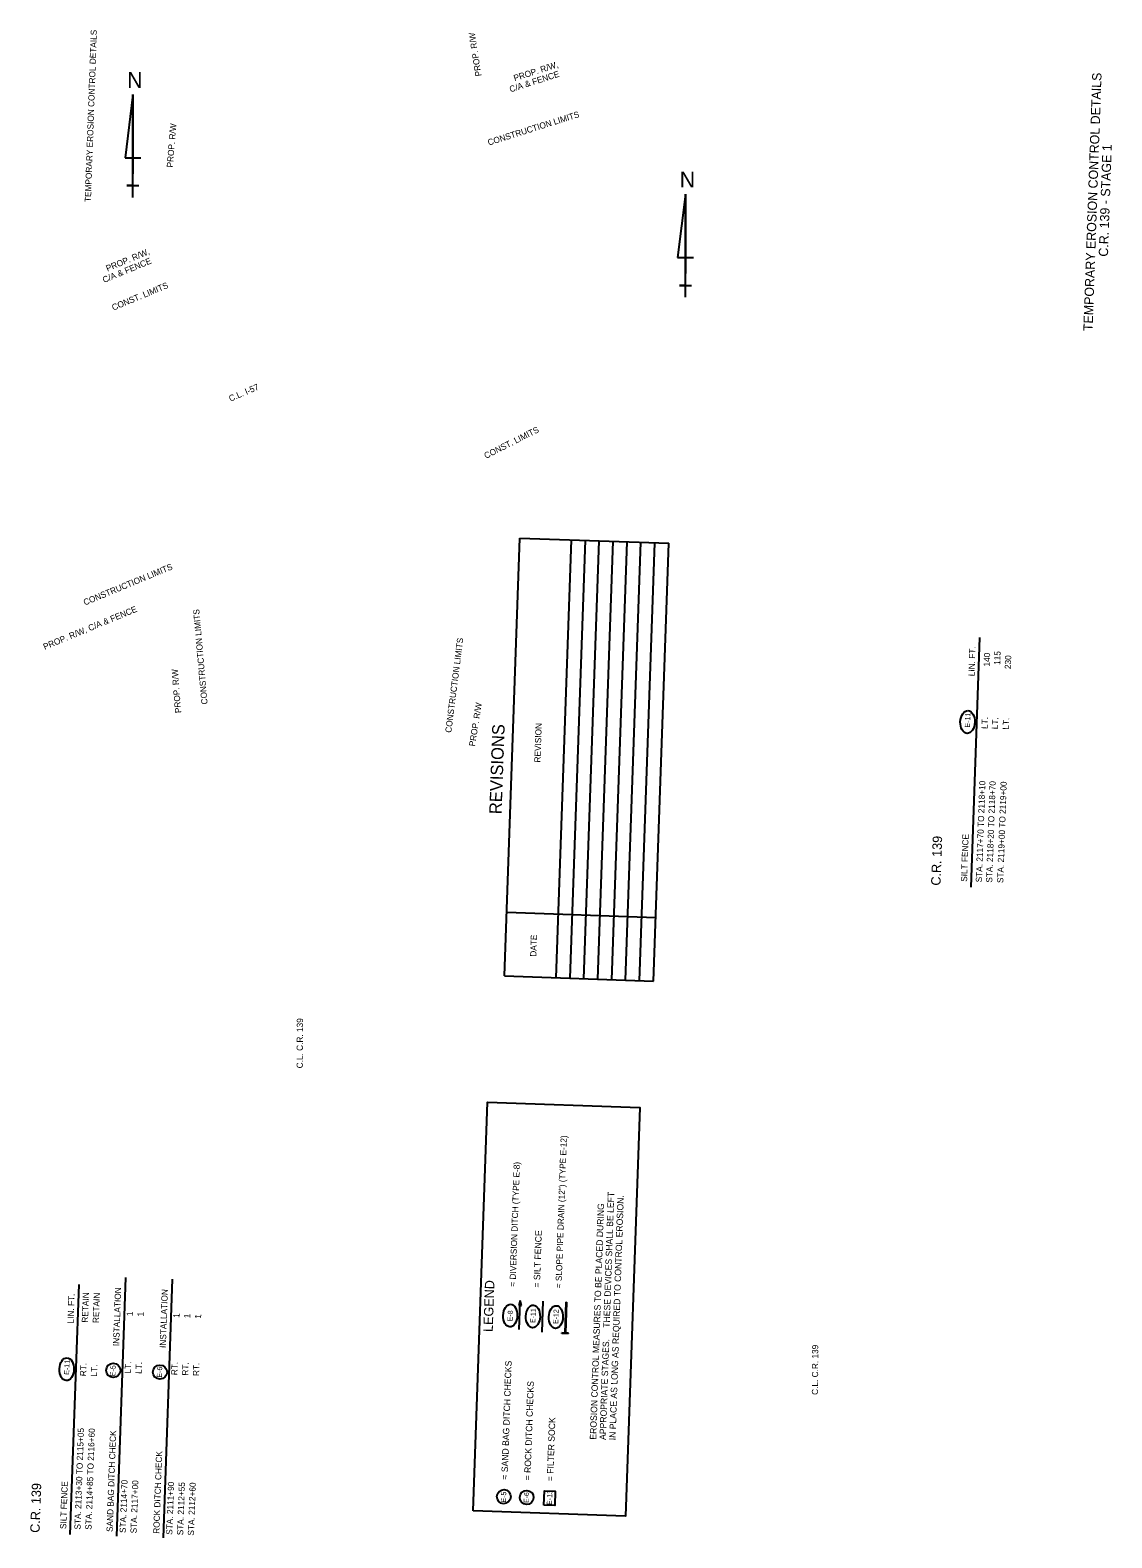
# Model space of a CAD drawing. Extents: x 1717345 to 1718395, y 765310 to 766772.
import ezdxf

# ---------------------------------------------------------------- set-up
doc = ezdxf.new("R2010")
doc.units = 0
for name, color, linetype in [('1', 7, 'Continuous'), ('44', 7, 'Continuous'), ('63', 7, 'Continuous'), ('Default', 7, 'Continuous'), ('G-ANNO-TEXT', 7, 'Continuous'), ('Level 1', 7, 'Continuous'), ('Level 44', 7, 'Continuous'), ('R_Draft', 7, 'Continuous')]:
    doc.layers.add(name, color=color, linetype=linetype)

msp = doc.modelspace()

# ---------------------------------------------------------------- linework, layer by layer
at = {"layer": '1'}
for points in [[(1717775.3, 765335.8), (1717789.1, 765732.2), (1717936.9, 765727), (1717923.1, 765330.6)], [(1717843.9, 765341.2), (1717844.4, 765355.2), (1717854.9, 765354.8), (1717854.4, 765340.8)]]:
    msp.add_lwpolyline(points, close=True, dxfattribs=at)
for centre in [(1717426, 765472), (1717471.3, 765470.3)]:
    msp.add_circle(centre, 6.88, dxfattribs=at)
for centre in [(1718255, 766100.8), (1717380.8, 765473.1)]:
    msp.add_ellipse(centre, major_axis=(0.4, 11), ratio=0.638788, dxfattribs=at)
at = {"layer": '44'}
for p, q in [((1718258.5, 765940.6), (1718267, 766182.9)), ((1717429.5, 765311.3), (1717438.2, 765562.2)), ((1717474.7, 765309.5), (1717483.5, 765560.4)), ((1717384.3, 765312.9), (1717392.8, 765555.2))]:
    msp.add_line(p, q, dxfattribs=at)
at = {"layer": '63'}
for p, q in [((1717445.1, 766709.4), (1717437.4, 766647.9)), ((1717445.1, 766609.4), (1717445.1, 766709.4)), ((1717445.1, 766709.4), (1717445.1, 766632.5)), ((1717437.4, 766647.9), (1717452.8, 766647.9)), ((1717445.1, 766609.4), (1717445.1, 766632.5)), ((1717445.1, 766621), (1717439.3, 766621)), ((1717439.3, 766621), (1717450.9, 766621)), ((1717445.1, 766609.4), (1717445.1, 766621)), ((1717981.3, 766612.8), (1717973.6, 766551.3)), ((1717981.3, 766512.8), (1717981.3, 766612.8)), ((1717981.3, 766612.8), (1717981.3, 766535.9)), ((1717973.6, 766551.3), (1717989, 766551.3)), ((1717981.3, 766524.3), (1717975.5, 766524.3)), ((1717975.5, 766524.3), (1717987.1, 766524.3)), ((1717981.3, 766512.8), (1717981.3, 766535.9)), ((1717981.3, 766512.8), (1717981.3, 766524.3))]:
    msp.add_line(p, q, dxfattribs=at)
at = {"layer": 'Default'}
for p, q in [((1717805.8, 765854.5), (1717820.6, 766279.2)), ((1717820.6, 766279.2), (1717965, 766274.2)), ((1717855.8, 765852.7), (1717870.6, 766277.5)), ((1717869.3, 765852.3), (1717884.1, 766277)), ((1717882.7, 765851.8), (1717897.6, 766276.5)), ((1717896.2, 765851.3), (1717911.1, 766276.1)), ((1717896.2, 765851.3), (1717911.1, 766276.1)), ((1717909.7, 765850.9), (1717924.6, 766275.6)), ((1717923.2, 765850.4), (1717938.1, 766275.1)), ((1717936.7, 765849.9), (1717951.5, 766274.7)), ((1717950.2, 765849.4), (1717965, 766274.2)), ((1717808, 765916.3), (1717952.4, 765911.2)), ((1717805.8, 765854.5), (1717950.2, 765849.4))]:
    msp.add_line(p, q, dxfattribs=at)
at = {"layer": 'Level 1'}
for p, q in [((1717821, 765539.7), (1717819.4, 765534.9)), ((1717819.4, 765534.9), (1717822.3, 765534.8)), ((1717820.7, 765538.4), (1717819.7, 765534.9)), ((1717820.8, 765538.4), (1717820.1, 765534.9)), ((1717820.9, 765538.4), (1717820.5, 765534.9)), ((1717822.3, 765534.8), (1717821, 765539.7)), ((1717821.5, 765534.9), (1717821.1, 765538.4)), ((1717821.2, 765534.9), (1717821.1, 765538.4)), ((1717821.9, 765534.8), (1717821.2, 765538.4))]:
    msp.add_line(p, q, dxfattribs=at)
msp.add_lwpolyline([(1717820, 765511.5), (1717820.9, 765538)], dxfattribs=at)
for centre, major_axis, ratio in [((1717811.2, 765525.1), (0.4, 11), 0.622952), ((1717833.3, 765524.3), (0.4, 11), 0.622952), ((1717855.5, 765523.7), (0.4, 11), 0.622952), ((1717805, 765349.5), (-0.23, -6.88), 0.97521), ((1717827.2, 765348.7), (-0.23, -6.88), 0.97521)]:
    msp.add_ellipse(centre, major_axis=major_axis, ratio=ratio, dxfattribs=at)
at = {"layer": 'Level 44'}
for p, q in [((1717865.3, 765538.1), (1717864.3, 765508.2)), ((1717865.8, 765538.1), (1717864.8, 765508.2)), ((1717865.3, 765538.1), (1717865.8, 765538.1)), ((1717864.3, 765508.2), (1717861.2, 765508.3)), ((1717861.2, 765507.8), (1717861.2, 765508.3)), ((1717867.9, 765507.6), (1717861.2, 765507.8)), ((1717867.9, 765508.1), (1717864.8, 765508.2)), ((1717867.9, 765507.6), (1717867.9, 765508.1))]:
    msp.add_line(p, q, dxfattribs=at)
msp.add_lwpolyline([(1717842.1, 765509), (1717843.1, 765539.1)], dxfattribs=at)

# ---------------------------------------------------------------- texts
at = {"layer": '1'}
for s, rotation, p in [('E-11', 88, (1718257.3, 766095.3)), ('E-11', 88, (1717383.1, 765467.6)), ('E-5 ', 88, (1717428, 765466.2)), ('E-6 ', 88, (1717473.2, 765464.8)), ('E-13', 87.6177, (1717851.6, 765341.3))]:
    msp.add_text(s, height=5, rotation=rotation, dxfattribs=at).set_placement(p)
at = {"layer": '44'}
for s, p in [('LIN. FT.', (1718261.7, 766145.1)), ('140', (1718276.5, 766154.5)), ('115', (1718286.6, 766156.1)), ('230', (1718297, 766152)), ('LT.', (1718274.4, 766094)), ('LT.', (1718284.4, 766093.7)), ('LT.', (1718295, 766093.3)), ('STA. 2117+70 TO 2118+10', (1718268.9, 765945.2)), ('STA. 2118+20 TO 2118+70', (1718278.9, 765944.9)), ('STA. 2119+00 TO 2119+00', (1718289.6, 765944.5)), ('SILT FENCE      ', (1718254.5, 765945.7)), ('LIN. FT.', (1717387.5, 765517.4)), ('RETAIN', (1717401.4, 765518.2)), ('RETAIN', (1717412, 765517.8)), ('INSTALLATION', (1717431.7, 765495.4)), ('INSTALLATION', (1717477, 765493.6)), ('1', (1717444.9, 765524.5)), ('1', (1717455.4, 765524.2)), ('1', (1717490.2, 765522.8)), ('1', (1717500.7, 765522.4)), ('1', (1717511.2, 765522)), ('RT.', (1717399.6, 765466.2)), ('LT.', (1717410.2, 765466)), ('LT.', (1717443, 765468.9)), ('LT.', (1717453.5, 765468.5)), ('RT.', (1717488.2, 765467.2)), ('RT.', (1717498.7, 765466.8)), ('RT.', (1717509.2, 765466.4)), ('STA. 2113+30 TO 2115+05', (1717394.2, 765317.5)), ('STA. 2114+85 TO 2116+60 ', (1717404.8, 765317.2)), ('SAND BAG DITCH CHECK', (1717425.4, 765315.2)), ('ROCK DITCH CHECK', (1717470.7, 765313.4)), ('SILT FENCE      ', (1717380.3, 765318)), ('STA. 2114+70', (1717438.1, 765314.2)), ('STA. 2117+00', (1717448.6, 765313.8)), ('STA. 2111+90', (1717483.3, 765312.4)), ('STA. 2112+55', (1717493.8, 765312)), ('STA. 2112+60', (1717504.3, 765311.7))]:
    msp.add_text(s, height=6, rotation=88, dxfattribs=at).set_placement(p)
at = {"layer": '63'}
for p in [(1717439.5, 766715.8), (1717975.7, 766619.2)]:
    msp.add_text('N', height=15.4, rotation=360, dxfattribs=at).set_placement(p)
at = {"layer": 'Default'}
for s, height, p in [('REVISION', 6, (1717840.5, 766061.4)), ('REVISIONS', 12, (1717802.8, 766011.2)), ('DATE', 6, (1717836.5, 765873.1))]:
    msp.add_text(s, height=height, rotation=88, dxfattribs=at).set_placement(p)
at = {"layer": 'G-ANNO-TEXT'}
for s, height, p in [('TEMPORARY EROSION CONTROL DETAILS', 6, (1717404.3, 766605)), ('TEMPORARY EROSION CONTROL DETAILS', 9, (1718376.3, 766479.8)), ('C.R. 139 - STAGE 1', 9, (1718391.2, 766552))]:
    msp.add_text(s, height=height, rotation=88, dxfattribs=at).set_placement(p)
at = {"layer": 'Level 1'}
for s, height, rotation, p in [('= SLOPE PIPE DRAIN (12") (TYPE E-12)', 6, 88, (1717861, 765551.5)), ('= DIVERSION DITCH (TYPE E-8)', 6, 88, (1717816.4, 765553.1)), ('THESE DEVICES SHALL BE LEFT', 6.25, 88.058, (1717907.7, 765513.2)), ('EROSION CONTROL MEASURES TO BE PLACED DURING', 6.25, 88.058, (1717894.6, 765404.7)), ('IN PLACE AS LONG AS REQUIRED TO CONTROL EROSION.', 6.25, 88.058, (1717913.4, 765404.1)), ('= SILT FENCE', 6.25, 88.058, (1717840, 765552.2)), ('E-8', 4.88, 88, (1717813.4, 765519.6)), ('E-11 ', 4.88, 88.058, (1717835.5, 765517.9)), ('E-12', 4.88, 88, (1717857.7, 765516.9)), ('APPROPRIATE STAGES. ', 6.25, 88.058, (1717904, 765404.4)), ('= SAND BAG DITCH CHECKS', 6.25, 88.058, (1717808.7, 765365.9)), ('= ROCK DITCH CHECKS', 6.25, 88.058, (1717830.9, 765365.2)), ('= FILTER SOCK', 6.25, 88, (1717852.9, 765364.4)), ('E-5 ', 4.88, 88.058, (1717807, 765343.8)), ('E-6 ', 4.88, 88.058, (1717829.1, 765343.3))]:
    msp.add_text(s, height=height, rotation=rotation, dxfattribs=at).set_placement(p)
at = {"layer": 'Level 44'}
for s, rotation, p in [('C.R. 139', 88, (1718228.7, 765942)), ('LEGEND', 88.058, (1717794.2, 765509.1)), ('C.R. 139', 88, (1717354.5, 765314.3))]:
    msp.add_text(s, height=9.14, rotation=rotation, dxfattribs=at).set_placement(p)
at = {"layer": 'R_Draft'}
for s, rotation, p in [('PROP. R/W', 99.0183, (1717783.5, 766727.5)), ('C/A & FENCE', 17.8147, (1717811.5, 766711.4)), ('PROP. R/W, ', 17.8147, (1717815.6, 766722.2)), ('CONSTRUCTION LIMITS', 17.4545, (1717790.4, 766659.8)), ('PROP. R/W', 85.3201, (1717483.8, 766638.4)), ('PROP. R/W, ', 22.5, (1717420.4, 766537.6)), ('C/A & FENCE', 22.5, (1717417.1, 766526.5)), ('CONST. LIMITS', 22.5, (1717426.1, 766499.7)), ('C.L. I-57', 23.2911, (1717539.7, 766411.4)), ('CONST. LIMITS', 26.8932, (1717787.7, 766355.9)), ('CONSTRUCTION LIMITS', 22.5, (1717398.5, 766213.7)), ('PROP. R/W, C/A & FENCE', 22.5, (1717359.5, 766170.7)), ('CONSTRUCTION LIMITS', 95.0845, (1717517.6, 766118.1)), ('CONSTRUCTION LIMITS', 82.7276, (1717754, 766090.1)), ('PROP. R/W', 94.6077, (1717492, 766109.7)), ('PROP. R/W', 80.8828, (1717777, 766076.8)), ('C.L. C.R. 139', 89.7759, (1717609.9, 765764.9)), ('C.L. C.R. 139', 89.7759, (1718109.9, 765448.2))]:
    msp.add_text(s, height=6, rotation=rotation, dxfattribs=at).set_placement(p)

doc.saveas('drawing.dxf')
